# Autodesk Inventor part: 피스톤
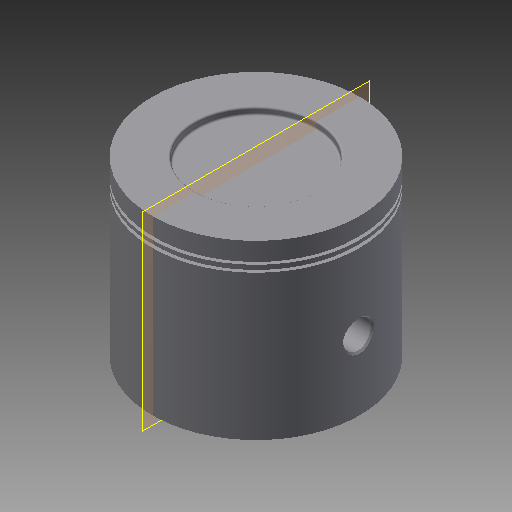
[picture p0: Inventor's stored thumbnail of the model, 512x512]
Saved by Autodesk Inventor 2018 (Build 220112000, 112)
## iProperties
Created: 2016-11
Part Number: 피스톤
Material: 강철, 탄소
Document SubType Name: Modeling
Designer: mduedu
Density: 7.87 g/cm^3
Mass: 410.128 g
Surface Area: 237.507 cm^2
Volume: 52.1129 cm^3
Appearance: 기본값
Author: mduedu
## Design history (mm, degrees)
sketch "스케치1"
  geometry: C1 r 30 at (0, 0); 1 further point
  constraints: 1 centre point, 1 coincident
  dimensions: "d0" = 60 diameter of C1
extrude "돌출1" new body sketch "스케치1" distance "d1" = 50; taper "d2" = 0 deg
sketch "스케치2"
  geometry: C1 r 28 at (0, 0); 1 further point
  constraints: 1 centre point, 1 coincident
  dimensions: "d3" = 56 diameter of C1
extrude "돌출2" cut sketch "스케치2" distance "d4" = 45; taper "d5" = 0 deg
sketch "스케치3"
  geometry: L1 (30, 0)-(30, 50) reference; L2 (30, 45)-(29, 45); L3 (29, 45)-(29, 44); L4 (29, 44)-(30, 44); L5 (30, 44)-(30, 45); L6 (30, 43)-(29, 43); L7 (29, 43)-(29, 42); L8 (29, 42)-(30, 42); L9 (30, 42)-(30, 43); L10 (30, 50)-(-30, 50) reference; L11 (0, 50)-(0, 0)
  constraints: 18 end point, 4 parallel, 3 equal length, 3 perpendicular, 2 horizontal, 2 point on line, 1 midpoint
  dimensions: "d6" = 1 distance of L2.start L2.end; "d8" = 5 distance between parallel lines of L10 L2; "d9" = 1 distance between parallel lines of L6 L4
revolve "회전1" sketch "스케치3" stored, may be unused: angle "d10" = 90 deg
node "작업 평면1"
sketch "스케치4"
  geometry: L1 (0, -22.978)-(45, -22.978) reference; L2 (45, -22.978)-(45, 22.978) reference; L3 (45, 22.978)-(0, 22.978) reference; L4 (0, 22.978)-(0, 25.377) reference; L5 (0, 25.377)-(42, 25.377) reference; L6 (42, 25.377)-(42, 24.187) reference; L7 (42, 24.187)-(43, 24.187) reference; L8 (43, 24.187)-(43, 25.377) reference; L9 (43, 25.377)-(44, 25.377) reference; L10 (44, 25.377)-(44, 24.187) reference; L11 (44, 24.187)-(45, 24.187) reference; L12 (45, 24.187)-(45, 25.377) reference; L13 (45, 25.377)-(50, 25.377) reference; L14 (50, 25.377)-(50, -25.377) reference; L15 (50, -25.377)-(45, -25.377) reference; L16 (45, -25.377)-(45, -24.187) reference; L17 (45, -24.187)-(44, -24.187) reference; L18 (44, -24.187)-(44, -25.377) reference; L19 (44, -25.377)-(43, -25.377) reference; L20 (43, -25.377)-(43, -24.187) reference; L21 (43, -24.187)-(42, -24.187) reference; L22 (42, -24.187)-(42, -25.377) reference; L23 (42, -25.377)-(0, -25.377) reference; L24 (0, -25.377)-(0, -22.978) reference; L25 (12.5, 22.978)-(45, 22.978); L26 (45, 22.978)-(45, -22.978); L27 (45, -22.978)-(12.5, -22.978); L28 (12.5, -22.978)-(12.5, 22.978); C1 r 7.5 at (20, 0); C2 r 4 at (20, 0); 1 further point
  constraints: 8 end point, 2 centre point, 2 parallel, 1 coincident, 1 horizontal, 1 horizontal alignment, 1 perpendicular, 1 point on line, 1 tangent
  dimensions: "d12" = 15 diameter of C1; "d13" = 8 diameter of C2; "d14" = 20 distance of point (0, 0) C1.centre
  node "절단 모서리 투영1"
extrude "돌출3" join sketch "스케치4" stored distance "d15" = 11.75; taper "d16" = 0 deg
extrude "돌출4" cut sketch "스케치4" extent not by distance; stored distance "d17" = 72; taper "d18" = 0 deg
fillet "모깎기2" dims "d20" = 3
chamfer "모따기1" distance "d21" = 0.5; stored, may be unused: second distance "d22" = 2, angle "d23" = 45 deg
chamfer "모따기2" distance "d24" = 0.5; stored, may be unused: second distance "d25" = 2, angle "d26" = 45 deg
sketch "스케치5"
  geometry: C1 r 17.5 at (0, 0); 1 further point
  constraints: 1 centre point, 1 coincident
  dimensions: "d27" = 35 diameter of C1
extrude "돌출5" cut sketch "스케치5" distance "d28" = 2; taper "d29" = 0 deg
fillet "모깎기3" dims "d30" = 0.5
node "솔리드1"
mirror "대칭1"
other parameters: "d11" = -16
